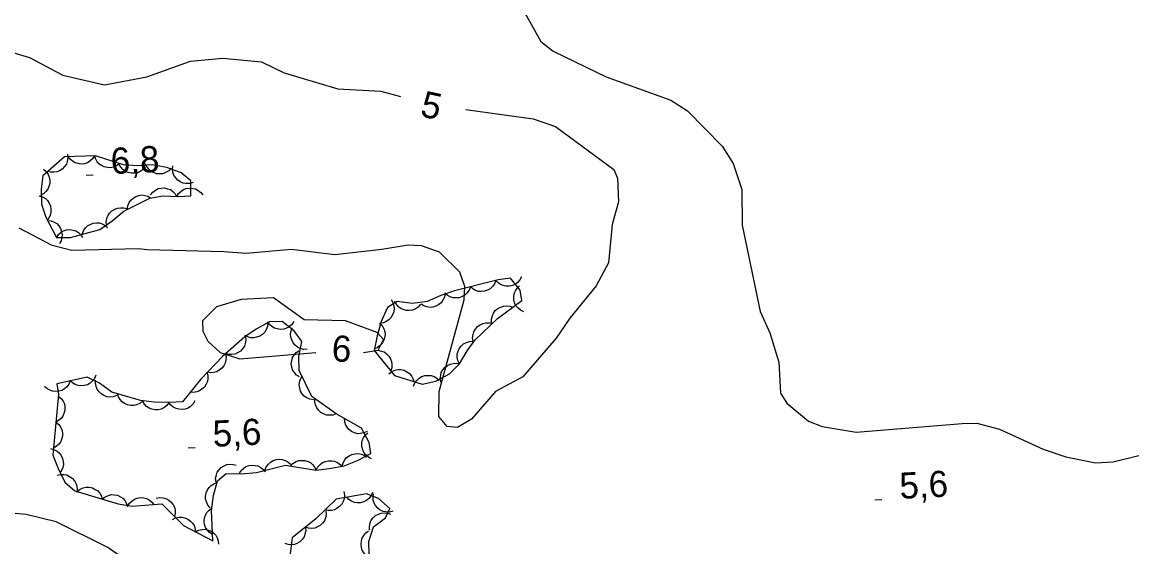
# Model space of a CAD drawing. Extents: x 336540 to 340074, y 5572036 to 5573747.
# Drawn here: x 336893.1 to 337020.3, y 5572816.6 to 5572876.8 of the extents above; entities that cross this region are included whole.
import ezdxf

# ---------------------------------------------------------------- set-up
doc = ezdxf.new("R2010")
doc.units = 0
for name, color, linetype in [('Niveau 1', 7, 'Continuous'), ('Niveau 2', 7, 'Continuous'), ('Niveau 3', 7, 'Continuous'), ('Niveau 44', 7, 'Continuous')]:
    doc.layers.add(name, color=color, linetype=linetype)

msp = doc.modelspace()

# ---------------------------------------------------------------- linework, layer by layer
at = {"layer": 'Niveau 1'}
for points in [[(336892.07, 5572873.27), (336893.96, 5572872.71), (336897.78, 5572870.69), (336902.57, 5572869.57), (336907.44, 5572870.51), (336912.42, 5572872.28), (336916.14, 5572872.65), (336920.55, 5572872.21), (336923.17, 5572870.97), (336929.33, 5572869.1), (336934.26, 5572868.83), (336936.48, 5572868.22)], [(336944, 5572866.74), (336951.69, 5572865.67), (336954.26, 5572864.78), (336960.95, 5572859.87), (336961.35, 5572858.87), (336961.48, 5572856.17), (336960.77, 5572853.57), (336960.33, 5572849.14), (336958.93, 5572846.52), (336955.91, 5572842.81), (336954.33, 5572840.51), (336950.5, 5572836.08), (336947.38, 5572834.41), (336944.65, 5572831.21), (336943.02, 5572830.26), (336941.83, 5572830.39), (336940.9, 5572831.52), (336940.94, 5572834.41), (336943.79, 5572844.91), (336943.87, 5572846.43), (336943.29, 5572848.1), (336940.96, 5572850.37), (336938.91, 5572851.11), (336937.37, 5572851.18), (336934.35, 5572850.69), (336928.97, 5572850.09), (336924.02, 5572850.68), (336918.81, 5572850.23), (336916.26, 5572850.43), (336907.46, 5572850.65), (336906.43, 5572850.78), (336898.82, 5572850.57), (336896.59, 5572851.13), (336892.78, 5572853.13)]]:
    msp.add_lwpolyline(points, dxfattribs=at)
at = {"layer": 'Niveau 2'}
for points in [[(336950.73, 5572877.82), (336952.58, 5572874.55), (336953.99, 5572873.42), (336960.06, 5572870.5), (336967.47, 5572867.82), (336969.4, 5572866.58), (336973.34, 5572862.54), (336974.63, 5572860.57), (336975.63, 5572857.57), (336975.65, 5572853.49), (336977.7, 5572843.57), (336978.84, 5572841.11), (336979.85, 5572837.77), (336980.04, 5572834.22), (336980.78, 5572833.07), (336983.25, 5572830.99), (336984.81, 5572830.38), (336988.73, 5572829.74), (337000.86, 5572830.71), (337002.55, 5572830.78), (337005.13, 5572830.08), (337010.15, 5572827.78), (337012.74, 5572826.89), (337016.16, 5572826.22), (337018.18, 5572826.32), (337024.2, 5572827.82)], [(336932.25, 5572838.88), (336933.92, 5572839.14), (336934.54, 5572840.36), (336933.82, 5572841.17), (336930.2, 5572842.52), (336925.46, 5572842.61), (336921.94, 5572845.13), (336918.22, 5572844.95), (336915.4, 5572844.11), (336913.8, 5572842.5), (336913.86, 5572841.33), (336914.42, 5572840.17), (336915.83, 5572838.88), (336918.07, 5572838.15), (336926.79, 5572838.89)], [(336948.07, 5572804.58), (336934.89, 5572807.63), (336927.8, 5572810.66), (336926.62, 5572810.61), (336924.6, 5572810.16), (336923.76, 5572810.12), (336919.3, 5572808.02), (336917.78, 5572807.94), (336916.07, 5572808.34), (336913.63, 5572809.6), (336907.66, 5572813.86), (336904.54, 5572815.39), (336902.96, 5572816.51), (336897.05, 5572819.44), (336893.61, 5572820.27), (336886.48, 5572820.92), (336883.74, 5572821.79), (336883.2, 5572822.28), (336880.96, 5572823.17), (336875.34, 5572826.97), (336872.22, 5572828.33), (336868.12, 5572828.97), (336864.58, 5572828.78), (336858.52, 5572827.97)]]:
    msp.add_lwpolyline(points, dxfattribs=at)
at = {"layer": 'Niveau 3'}
for p, q in [((336900.47, 5572859.23), (336901.27, 5572859.27)), ((336912.16, 5572827.95), (336912.96, 5572827.99)), ((336990.86, 5572821.98), (336991.66, 5572822.02))]:
    msp.add_line(p, q, dxfattribs=at)
at = {"layer": 'Niveau 44'}
for points in [[(336897.06, 5572852.07), (336898.67, 5572852.07), (336902.05, 5572852.98), (336903.43, 5572853.95), (336904.77, 5572855.08), (336907.76, 5572856.56), (336909.26, 5572856.86), (336911.02, 5572856.75), (336912.45, 5572856.85), (336912.46, 5572858.57), (336911.37, 5572859.47), (336909.73, 5572860.09), (336908.05, 5572860.38), (336906.3, 5572860.27), (336904.75, 5572860.4), (336901.55, 5572861.43), (336897.99, 5572861.32), (336895.49, 5572859.15), (336895.33, 5572857.62), (336895.37, 5572855.87), (336895.84, 5572854.39), (336897.06, 5572852.07)], [(336898.32, 5572861.61), (336898.37, 5572861.19), (336898.3, 5572860.79), (336898.2, 5572860.48), (336898, 5572860.19), (336897.74, 5572859.92), (336897.42, 5572859.72), (336897.12, 5572859.58), (336896.77, 5572859.54), (336896.4, 5572859.55), (336896.05, 5572859.64)], [(336901.43, 5572861.43), (336901.2, 5572861.07), (336900.89, 5572860.81), (336900.62, 5572860.63), (336900.28, 5572860.53), (336899.91, 5572860.48), (336899.53, 5572860.54), (336899.22, 5572860.61), (336898.92, 5572860.8), (336898.64, 5572861.04), (336898.43, 5572861.33)], [(336904.29, 5572860.55), (336903.96, 5572860.29), (336903.58, 5572860.14), (336903.26, 5572860.07), (336902.91, 5572860.09), (336902.55, 5572860.17), (336902.21, 5572860.34), (336901.93, 5572860.52), (336901.71, 5572860.8), (336901.53, 5572861.12), (336901.43, 5572861.47)], [(336895.57, 5572859.89), (336895.89, 5572859.62), (336896.11, 5572859.28), (336896.25, 5572858.99), (336896.31, 5572858.64), (336896.3, 5572858.27), (336896.2, 5572857.9), (336896.08, 5572857.6), (336895.85, 5572857.32), (336895.57, 5572857.08), (336895.26, 5572856.91)], [(336907.25, 5572860.19), (336906.99, 5572859.86), (336906.66, 5572859.64), (336906.36, 5572859.49), (336906.01, 5572859.43), (336905.65, 5572859.43), (336905.27, 5572859.52), (336904.97, 5572859.64), (336904.69, 5572859.85), (336904.44, 5572860.13), (336904.27, 5572860.44)], [(336910.22, 5572860), (336909.93, 5572859.7), (336909.58, 5572859.51), (336909.27, 5572859.38), (336908.92, 5572859.35), (336908.55, 5572859.38), (336908.19, 5572859.51), (336907.9, 5572859.65), (336907.64, 5572859.89), (336907.41, 5572860.19), (336907.27, 5572860.52)], [(336912.72, 5572858.36), (336912.32, 5572858.24), (336911.91, 5572858.24), (336911.58, 5572858.29), (336911.26, 5572858.44), (336910.96, 5572858.65), (336910.71, 5572858.94), (336910.52, 5572859.21), (336910.42, 5572859.54), (336910.37, 5572859.91), (336910.4, 5572860.27)], [(336907.85, 5572856.95), (336908.1, 5572857.28), (336908.43, 5572857.51), (336908.73, 5572857.67), (336909.07, 5572857.74), (336909.44, 5572857.75), (336909.81, 5572857.66), (336910.12, 5572857.55), (336910.4, 5572857.34), (336910.66, 5572857.07), (336910.84, 5572856.76)], [(336910.84, 5572856.74), (336911.05, 5572857.1), (336911.35, 5572857.38), (336911.62, 5572857.57), (336911.95, 5572857.68), (336912.31, 5572857.74), (336912.7, 5572857.7), (336913.02, 5572857.64), (336913.32, 5572857.46), (336913.61, 5572857.23), (336913.83, 5572856.95)], [(336895.06, 5572856.86), (336895.46, 5572856.74), (336895.8, 5572856.52), (336896.05, 5572856.3), (336896.23, 5572856), (336896.38, 5572855.66), (336896.43, 5572855.28), (336896.44, 5572854.96), (336896.35, 5572854.62), (336896.19, 5572854.28), (336895.96, 5572854)], [(336905.17, 5572855.28), (336905.23, 5572855.69), (336905.4, 5572856.06), (336905.58, 5572856.34), (336905.84, 5572856.57), (336906.16, 5572856.77), (336906.52, 5572856.88), (336906.84, 5572856.94), (336907.19, 5572856.89), (336907.55, 5572856.79), (336907.86, 5572856.61)], [(336902.82, 5572853.44), (336902.78, 5572853.85), (336902.85, 5572854.25), (336902.96, 5572854.56), (336903.16, 5572854.85), (336903.42, 5572855.11), (336903.75, 5572855.31), (336904.05, 5572855.44), (336904.4, 5572855.48), (336904.77, 5572855.47), (336905.11, 5572855.37)], [(336896.03, 5572854.03), (336896.45, 5572853.98), (336896.82, 5572853.82), (336897.1, 5572853.65), (336897.34, 5572853.39), (336897.54, 5572853.08), (336897.66, 5572852.72), (336897.73, 5572852.4), (336897.69, 5572852.05), (336897.6, 5572851.69), (336897.43, 5572851.37)], [(336900.01, 5572852.43), (336900.15, 5572852.83), (336900.39, 5572853.16), (336900.61, 5572853.4), (336900.92, 5572853.57), (336901.27, 5572853.7), (336901.65, 5572853.73), (336901.97, 5572853.73), (336902.31, 5572853.62), (336902.64, 5572853.45), (336902.91, 5572853.21)], [(336897.06, 5572852.07), (336897.29, 5572852.42), (336897.61, 5572852.67), (336897.89, 5572852.84), (336898.23, 5572852.93), (336898.6, 5572852.97), (336898.98, 5572852.9), (336899.29, 5572852.81), (336899.59, 5572852.62), (336899.86, 5572852.37), (336900.06, 5572852.07)], [(336933.49, 5572839.09), (336935.82, 5572836.23), (336938.99, 5572835.23), (336940.55, 5572835.59), (336942.1, 5572836.41), (336943.24, 5572837.57), (336944.12, 5572839.08), (336945.05, 5572840.34), (336947.6, 5572842.77), (336950.4, 5572844.84), (336950.2, 5572846.04), (336949.12, 5572847.4), (336947.67, 5572847.21), (336942.68, 5572845.95), (336941.13, 5572845.42), (336939.54, 5572844.71), (336937.86, 5572844.51), (336936.13, 5572844.72), (336934.99, 5572844.02), (336934.27, 5572842.43), (336933.81, 5572840.79), (336933.49, 5572839.09)], [(336950.37, 5572847.56), (336950.19, 5572847.19), (336949.91, 5572846.9), (336949.65, 5572846.69), (336949.32, 5572846.56), (336948.96, 5572846.48), (336948.58, 5572846.49), (336948.26, 5572846.54), (336947.94, 5572846.69), (336947.64, 5572846.91), (336947.4, 5572847.17)], [(336944.5, 5572846.41), (336944.36, 5572846.02), (336944.11, 5572845.69), (336943.88, 5572845.45), (336943.57, 5572845.28), (336943.22, 5572845.16), (336942.84, 5572845.13), (336942.52, 5572845.14), (336942.18, 5572845.26), (336941.86, 5572845.43), (336941.59, 5572845.67)], [(336947.41, 5572847.14), (336947.26, 5572846.75), (336947.02, 5572846.43), (336946.79, 5572846.19), (336946.48, 5572846.02), (336946.13, 5572845.9), (336945.75, 5572845.87), (336945.42, 5572845.88), (336945.09, 5572845.99), (336944.77, 5572846.17), (336944.5, 5572846.41)], [(336950.62, 5572843.55), (336950.24, 5572843.72), (336949.93, 5572843.99), (336949.72, 5572844.24), (336949.57, 5572844.56), (336949.48, 5572844.92), (336949.48, 5572845.3), (336949.51, 5572845.63), (336949.66, 5572845.95), (336949.86, 5572846.26), (336950.12, 5572846.5)], [(336935.41, 5572844.95), (336935.63, 5572844.6), (336935.73, 5572844.21), (336935.78, 5572843.88), (336935.72, 5572843.53), (336935.59, 5572843.18), (336935.38, 5572842.86), (336935.17, 5572842.61), (336934.87, 5572842.43), (336934.53, 5572842.28), (336934.18, 5572842.22)], [(336938.8, 5572844.4), (336938.52, 5572844.08), (336938.18, 5572843.86), (336937.88, 5572843.73), (336937.53, 5572843.68), (336937.16, 5572843.69), (336936.79, 5572843.8), (336936.49, 5572843.93), (336936.22, 5572844.15), (336935.99, 5572844.44), (336935.82, 5572844.76)], [(336941.6, 5572845.63), (336941.53, 5572845.22), (336941.34, 5572844.86), (336941.15, 5572844.58), (336940.88, 5572844.36), (336940.56, 5572844.18), (336940.19, 5572844.09), (336939.86, 5572844.04), (336939.52, 5572844.1), (336939.16, 5572844.22), (336938.86, 5572844.41)], [(336946.93, 5572842.28), (336946.91, 5572842.69), (336947.02, 5572843.09), (336947.14, 5572843.39), (336947.36, 5572843.67), (336947.64, 5572843.91), (336947.98, 5572844.09), (336948.29, 5572844.2), (336948.64, 5572844.22), (336949.01, 5572844.18), (336949.34, 5572844.06)], [(336929.14, 5572831.85), (336926.35, 5572833.81), (336924.9, 5572836.79), (336924.86, 5572838.43), (336925.17, 5572840.15), (336924.32, 5572841.35), (336922.93, 5572842.41), (336921.49, 5572842.38), (336919.96, 5572841.54), (336918.67, 5572840.66), (336916.08, 5572838.43), (336913.6, 5572835.81), (336911.53, 5572833.23), (336910.03, 5572833.12), (336908.27, 5572833.19), (336906.69, 5572833.38), (336903.4, 5572834.33), (336902, 5572835.37), (336900.57, 5572836.06), (336897.11, 5572835.29), (336897.29, 5572834.08), (336896.66, 5572827.1), (336897.25, 5572825.57), (336898.03, 5572824), (336899.18, 5572822.99), (336904.13, 5572821.53), (336905.74, 5572821.26), (336909.15, 5572821.51), (336911.62, 5572819.03), (336914.98, 5572817.25), (336914.85, 5572820.76), (336915.07, 5572822.46), (336915.52, 5572824.15), (336916.52, 5572824.99), (336918.28, 5572824.96), (336919.99, 5572825.1), (336923.32, 5572825.94), (336926.78, 5572825.36), (336928.33, 5572825.57), (336930.05, 5572825.88), (336931.57, 5572826.47), (336933.1, 5572827.3), (336932.91, 5572828.53), (336932.01, 5572830.2), (336929.14, 5572831.85)], [(336921.29, 5572842.27), (336921.25, 5572841.85), (336921.1, 5572841.48), (336920.93, 5572841.19), (336920.68, 5572840.95), (336920.37, 5572840.74), (336920.01, 5572840.62), (336919.69, 5572840.54), (336919.34, 5572840.57), (336918.98, 5572840.66), (336918.66, 5572840.83)], [(336924.26, 5572842.44), (336924.03, 5572842.09), (336923.72, 5572841.82), (336923.44, 5572841.65), (336923.11, 5572841.55), (336922.74, 5572841.51), (336922.36, 5572841.57), (336922.04, 5572841.65), (336921.75, 5572841.84), (336921.47, 5572842.08), (336921.26, 5572842.38)], [(336934.08, 5572842.24), (336934.38, 5572841.95), (336934.57, 5572841.59), (336934.69, 5572841.28), (336934.72, 5572840.93), (336934.68, 5572840.56), (336934.55, 5572840.2), (336934.4, 5572839.91), (336934.16, 5572839.66), (336933.86, 5572839.43), (336933.53, 5572839.29)], [(336944.83, 5572840.13), (336944.76, 5572840.54), (336944.81, 5572840.94), (336944.9, 5572841.26), (336945.08, 5572841.56), (336945.32, 5572841.84), (336945.64, 5572842.05), (336945.93, 5572842.21), (336946.28, 5572842.27), (336946.65, 5572842.27), (336947, 5572842.2)], [(336925.81, 5572839.24), (336925.4, 5572839.23), (336925, 5572839.34), (336924.7, 5572839.47), (336924.43, 5572839.7), (336924.19, 5572839.98), (336924.03, 5572840.33), (336923.92, 5572840.63), (336923.9, 5572840.99), (336923.95, 5572841.35), (336924.08, 5572841.69)], [(336918.73, 5572840.71), (336918.78, 5572840.3), (336918.7, 5572839.9), (336918.6, 5572839.58), (336918.4, 5572839.29), (336918.15, 5572839.03), (336917.82, 5572838.83), (336917.52, 5572838.69), (336917.17, 5572838.65), (336916.8, 5572838.66), (336916.46, 5572838.75)], [(336943.24, 5572837.58), (336943.06, 5572837.95), (336943, 5572838.35), (336942.99, 5572838.68), (336943.09, 5572839.02), (336943.24, 5572839.36), (336943.49, 5572839.65), (336943.72, 5572839.88), (336944.04, 5572840.03), (336944.39, 5572840.14), (336944.75, 5572840.17)], [(336916.42, 5572838.79), (336916.51, 5572838.38), (336916.48, 5572837.98), (336916.41, 5572837.65), (336916.24, 5572837.34), (336916.01, 5572837.06), (336915.71, 5572836.83), (336915.43, 5572836.66), (336915.08, 5572836.58), (336914.71, 5572836.55), (336914.36, 5572836.61)], [(336924.92, 5572836.07), (336924.57, 5572836.29), (336924.3, 5572836.6), (336924.12, 5572836.88), (336924.03, 5572837.22), (336923.98, 5572837.58), (336924.04, 5572837.96), (336924.12, 5572838.28), (336924.31, 5572838.58), (336924.55, 5572838.86), (336924.84, 5572839.07)], [(336933.49, 5572839.09), (336933.91, 5572839.13), (336934.3, 5572839.04), (336934.62, 5572838.93), (336934.9, 5572838.73), (336935.16, 5572838.46), (336935.35, 5572838.13), (336935.48, 5572837.83), (336935.51, 5572837.48), (336935.49, 5572837.11), (336935.38, 5572836.76)], [(336941.14, 5572835.43), (336941.06, 5572835.84), (336941.1, 5572836.25), (336941.17, 5572836.57), (336941.35, 5572836.88), (336941.58, 5572837.16), (336941.89, 5572837.39), (336942.18, 5572837.55), (336942.52, 5572837.62), (336942.89, 5572837.64), (336943.24, 5572837.57)], [(336901.57, 5572836.28), (336901.42, 5572835.89), (336901.16, 5572835.58), (336900.93, 5572835.35), (336900.61, 5572835.18), (336900.26, 5572835.07), (336899.88, 5572835.05), (336899.55, 5572835.07), (336899.22, 5572835.2), (336898.9, 5572835.38), (336898.64, 5572835.63)], [(336914.29, 5572836.67), (336914.41, 5572836.27), (336914.42, 5572835.86), (336914.37, 5572835.54), (336914.23, 5572835.22), (336914.03, 5572834.91), (336913.74, 5572834.65), (336913.47, 5572834.46), (336913.14, 5572834.36), (336912.77, 5572834.3), (336912.41, 5572834.33)], [(336926.53, 5572833.44), (336926.12, 5572833.5), (336925.75, 5572833.67), (336925.47, 5572833.85), (336925.24, 5572834.12), (336925.05, 5572834.43), (336924.94, 5572834.8), (336924.88, 5572835.12), (336924.93, 5572835.47), (336925.04, 5572835.83), (336925.22, 5572836.14)], [(336935.16, 5572836.44), (336935.49, 5572836.7), (336935.87, 5572836.85), (336936.19, 5572836.93), (336936.54, 5572836.91), (336936.9, 5572836.83), (336937.24, 5572836.65), (336937.52, 5572836.48), (336937.74, 5572836.2), (336937.92, 5572835.88), (336938.02, 5572835.53)], [(336938, 5572835), (336938.15, 5572835.39), (336938.4, 5572835.71), (336938.64, 5572835.94), (336938.95, 5572836.11), (336939.3, 5572836.22), (336939.68, 5572836.24), (336940.01, 5572836.23), (336940.34, 5572836.11), (336940.66, 5572835.92), (336940.93, 5572835.68)], [(336898.64, 5572835.63), (336898.49, 5572835.24), (336898.24, 5572834.92), (336898, 5572834.69), (336897.68, 5572834.53), (336897.33, 5572834.42), (336896.95, 5572834.4), (336896.62, 5572834.42), (336896.29, 5572834.55), (336895.97, 5572834.73), (336895.71, 5572834.98)], [(336903.96, 5572833.92), (336903.56, 5572833.78), (336903.16, 5572833.76), (336902.83, 5572833.79), (336902.5, 5572833.92), (336902.19, 5572834.12), (336901.92, 5572834.39), (336901.72, 5572834.65), (336901.6, 5572834.98), (336901.53, 5572835.35), (336901.55, 5572835.71)], [(336897.27, 5572833.87), (336897.59, 5572833.61), (336897.82, 5572833.27), (336897.97, 5572832.97), (336898.03, 5572832.63), (336898.03, 5572832.26), (336897.93, 5572831.89), (336897.81, 5572831.58), (336897.59, 5572831.31), (336897.32, 5572831.06), (336897, 5572830.88)], [(336906.95, 5572833.31), (336906.63, 5572833.04), (336906.25, 5572832.88), (336905.93, 5572832.79), (336905.58, 5572832.8), (336905.22, 5572832.87), (336904.87, 5572833.04), (336904.6, 5572833.21), (336904.37, 5572833.48), (336904.18, 5572833.8), (336904.06, 5572834.14)], [(336909.95, 5572833.12), (336909.7, 5572832.79), (336909.37, 5572832.54), (336909.08, 5572832.38), (336908.74, 5572832.31), (336908.37, 5572832.29), (336908, 5572832.37), (336907.69, 5572832.47), (336907.4, 5572832.67), (336907.14, 5572832.94), (336906.95, 5572833.24)], [(336912.94, 5572833.33), (336912.73, 5572832.97), (336912.43, 5572832.69), (336912.16, 5572832.5), (336911.83, 5572832.39), (336911.47, 5572832.33), (336911.09, 5572832.36), (336910.77, 5572832.43), (336910.46, 5572832.6), (336910.17, 5572832.83), (336909.95, 5572833.11)], [(336929.14, 5572831.85), (336928.75, 5572831.7), (336928.34, 5572831.67), (336928.01, 5572831.69), (336927.68, 5572831.82), (336927.36, 5572832), (336927.09, 5572832.27), (336926.89, 5572832.52), (336926.76, 5572832.85), (336926.68, 5572833.21), (336926.69, 5572833.57)], [(336897, 5572830.88), (336897.33, 5572830.62), (336897.55, 5572830.28), (336897.7, 5572829.99), (336897.76, 5572829.64), (336897.76, 5572829.27), (336897.66, 5572828.9), (336897.54, 5572828.6), (336897.32, 5572828.32), (336897.05, 5572828.07), (336896.73, 5572827.9)], [(336932.67, 5572829.82), (336932.3, 5572829.64), (336931.89, 5572829.57), (336931.56, 5572829.56), (336931.23, 5572829.65), (336930.89, 5572829.81), (336930.59, 5572830.05), (336930.37, 5572830.29), (336930.21, 5572830.6), (336930.1, 5572830.96), (336930.07, 5572831.31)], [(336933.19, 5572826.69), (336932.82, 5572826.86), (336932.52, 5572827.14), (336932.3, 5572827.39), (336932.16, 5572827.71), (336932.07, 5572828.07), (336932.08, 5572828.45), (336932.12, 5572828.78), (336932.27, 5572829.1), (336932.47, 5572829.41), (336932.74, 5572829.65)], [(336896.37, 5572827.85), (336896.78, 5572827.75), (336897.13, 5572827.55), (336897.39, 5572827.35), (336897.6, 5572827.06), (336897.76, 5572826.73), (336897.84, 5572826.36), (336897.87, 5572826.03), (336897.79, 5572825.69), (336897.66, 5572825.34), (336897.45, 5572825.05)], [(336929.82, 5572825.79), (336929.91, 5572826.2), (336930.11, 5572826.55), (336930.31, 5572826.81), (336930.6, 5572827.02), (336930.93, 5572827.18), (336931.3, 5572827.26), (336931.63, 5572827.29), (336931.97, 5572827.22), (336932.32, 5572827.08), (336932.61, 5572826.87)], [(336915.36, 5572824.01), (336915.31, 5572824.43), (336915.39, 5572824.83), (336915.5, 5572825.14), (336915.7, 5572825.43), (336915.96, 5572825.69), (336916.29, 5572825.88), (336916.59, 5572826.02), (336916.94, 5572826.06), (336917.31, 5572826.04), (336917.65, 5572825.94)], [(336918, 5572824.94), (336918.21, 5572825.3), (336918.5, 5572825.58), (336918.77, 5572825.78), (336919.1, 5572825.89), (336919.46, 5572825.96), (336919.84, 5572825.92), (336920.16, 5572825.86), (336920.47, 5572825.69), (336920.76, 5572825.46), (336920.99, 5572825.18)], [(336920.96, 5572825.35), (336921.11, 5572825.74), (336921.35, 5572826.06), (336921.58, 5572826.3), (336921.89, 5572826.47), (336922.24, 5572826.59), (336922.62, 5572826.62), (336922.95, 5572826.61), (336923.28, 5572826.5), (336923.6, 5572826.32), (336923.87, 5572826.08)], [(336923.88, 5572825.85), (336924.17, 5572826.15), (336924.52, 5572826.35), (336924.83, 5572826.47), (336925.18, 5572826.5), (336925.55, 5572826.47), (336925.91, 5572826.35), (336926.21, 5572826.21), (336926.46, 5572825.97), (336926.69, 5572825.68), (336926.84, 5572825.35)], [(336926.84, 5572825.37), (336927.03, 5572825.74), (336927.3, 5572826.04), (336927.56, 5572826.25), (336927.89, 5572826.38), (336928.25, 5572826.46), (336928.63, 5572826.45), (336928.95, 5572826.41), (336929.27, 5572826.25), (336929.57, 5572826.04), (336929.81, 5572825.77)], [(336897.13, 5572824.79), (336897.54, 5572824.89), (336897.94, 5572824.88), (336898.27, 5572824.82), (336898.58, 5572824.66), (336898.88, 5572824.44), (336899.12, 5572824.15), (336899.3, 5572823.87), (336899.39, 5572823.53), (336899.43, 5572823.16), (336899.39, 5572822.81)], [(336899.45, 5572822.91), (336899.77, 5572823.18), (336900.14, 5572823.33), (336900.46, 5572823.42), (336900.81, 5572823.41), (336901.18, 5572823.34), (336901.52, 5572823.17), (336901.8, 5572822.99), (336902.02, 5572822.72), (336902.21, 5572822.41), (336902.32, 5572822.06)], [(336914.69, 5572821.04), (336914.42, 5572821.36), (336914.25, 5572821.73), (336914.16, 5572822.05), (336914.16, 5572822.4), (336914.22, 5572822.76), (336914.38, 5572823.11), (336914.55, 5572823.39), (336914.81, 5572823.63), (336915.12, 5572823.82), (336915.46, 5572823.94)], [(336902.32, 5572822.06), (336902.64, 5572822.33), (336903.02, 5572822.48), (336903.34, 5572822.57), (336903.69, 5572822.56), (336904.05, 5572822.49), (336904.4, 5572822.32), (336904.67, 5572822.15), (336904.9, 5572821.88), (336905.09, 5572821.56), (336905.2, 5572821.21)], [(336905.22, 5572821.22), (336905.43, 5572821.58), (336905.73, 5572821.86), (336906, 5572822.05), (336906.33, 5572822.17), (336906.69, 5572822.23), (336907.08, 5572822.19), (336907.4, 5572822.13), (336907.7, 5572821.96), (336907.99, 5572821.72), (336908.22, 5572821.44)], [(336908.49, 5572822.17), (336908.9, 5572822.25), (336909.3, 5572822.21), (336909.62, 5572822.13), (336909.93, 5572821.95), (336910.21, 5572821.71), (336910.43, 5572821.4), (336910.59, 5572821.12), (336910.66, 5572820.77), (336910.68, 5572820.4), (336910.61, 5572820.05)], [(336923.84, 5572815.76), (336929.94, 5572811.48), (336933.44, 5572807.99), (336934.89, 5572807.01), (336936.27, 5572806.52), (336937.89, 5572807.14), (336937.22, 5572808.37), (336936.2, 5572809.79), (336934.98, 5572813.04), (336934.02, 5572814.43), (336932.91, 5572815.79), (336932.86, 5572817.21), (336933.41, 5572818.86), (336934.77, 5572819.9), (336935.28, 5572820.97), (336933.98, 5572822.14), (336932.58, 5572822.67), (336929.12, 5572822.05), (336926.79, 5572819.78), (336924.07, 5572817.6), (336923.84, 5572815.76)], [(336930, 5572822.91), (336930.07, 5572822.5), (336930.03, 5572822.09), (336929.94, 5572821.77), (336929.76, 5572821.47), (336929.52, 5572821.19), (336929.21, 5572820.97), (336928.92, 5572820.82), (336928.57, 5572820.75), (336928.2, 5572820.74), (336927.85, 5572820.81)], [(336933.28, 5572822.8), (336933.11, 5572822.41), (336932.85, 5572822.11), (336932.6, 5572821.89), (336932.28, 5572821.74), (336931.92, 5572821.64), (336931.54, 5572821.64), (336931.22, 5572821.67), (336930.89, 5572821.81), (336930.58, 5572822.01), (336930.33, 5572822.27)], [(336935.63, 5572820.66), (336935.22, 5572820.56), (336934.82, 5572820.58), (336934.49, 5572820.64), (336934.18, 5572820.8), (336933.88, 5572821.02), (336933.64, 5572821.32), (336933.47, 5572821.6), (336933.38, 5572821.94), (336933.35, 5572822.31), (336933.4, 5572822.66)], [(336914.95, 5572818.01), (336914.6, 5572818.23), (336914.33, 5572818.54), (336914.15, 5572818.81), (336914.05, 5572819.15), (336914, 5572819.52), (336914.05, 5572819.9), (336914.13, 5572820.21), (336914.31, 5572820.51), (336914.55, 5572820.8), (336914.84, 5572821.01)], [(336927.95, 5572820.71), (336927.98, 5572820.29), (336927.89, 5572819.89), (336927.78, 5572819.58), (336927.57, 5572819.3), (336927.3, 5572819.04), (336926.97, 5572818.86), (336926.67, 5572818.73), (336926.32, 5572818.7), (336925.95, 5572818.72), (336925.6, 5572818.83)], [(336932.96, 5572818.51), (336932.93, 5572818.93), (336933.03, 5572819.33), (336933.15, 5572819.63), (336933.36, 5572819.91), (336933.64, 5572820.16), (336933.98, 5572820.34), (336934.28, 5572820.46), (336934.63, 5572820.49), (336935, 5572820.45), (336935.34, 5572820.34)], [(336910.35, 5572819.7), (336910.72, 5572819.9), (336911.12, 5572819.98), (336911.45, 5572820), (336911.79, 5572819.92), (336912.13, 5572819.77), (336912.44, 5572819.54), (336912.67, 5572819.31), (336912.84, 5572819.01), (336912.96, 5572818.66), (336913, 5572818.3)], [(336913, 5572818.3), (336913.37, 5572818.49), (336913.77, 5572818.57), (336914.1, 5572818.59), (336914.44, 5572818.51), (336914.78, 5572818.37), (336915.09, 5572818.14), (336915.32, 5572817.91), (336915.49, 5572817.6), (336915.61, 5572817.25), (336915.65, 5572816.89)], [(336925.6, 5572818.83), (336925.64, 5572818.41), (336925.55, 5572818.02), (336925.44, 5572817.71), (336925.23, 5572817.42), (336924.96, 5572817.17), (336924.63, 5572816.98), (336924.33, 5572816.85), (336923.98, 5572816.82), (336923.61, 5572816.85), (336923.26, 5572816.95)], [(336932.92, 5572815.38), (336932.57, 5572815.6), (336932.3, 5572815.91), (336932.12, 5572816.19), (336932.02, 5572816.52), (336931.97, 5572816.89), (336932.03, 5572817.27), (336932.1, 5572817.59), (336932.29, 5572817.89), (336932.53, 5572818.17), (336932.82, 5572818.38)]]:
    msp.add_lwpolyline(points, dxfattribs=at)

# ---------------------------------------------------------------- texts
at = {"layer": 'Niveau 1'}
msp.add_text('5', height=3, rotation=347.506, dxfattribs=at).set_placement((336938.64, 5572866))
at = {"layer": 'Niveau 2'}
msp.add_text('6', height=3, rotation=357.0427, dxfattribs=at).set_placement((336928.56, 5572837.87))
at = {"layer": 'Niveau 3'}
for s, p in [('6,8    ', (336903.35, 5572859.33)), ('5,6    ', (336915.04, 5572828.05)), ('5,6    ', (336993.74, 5572822.08))]:
    msp.add_text(s, height=3, rotation=2.7712, dxfattribs=at).set_placement(p)

doc.saveas('drawing.dxf')
